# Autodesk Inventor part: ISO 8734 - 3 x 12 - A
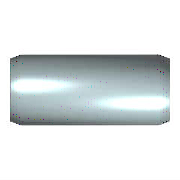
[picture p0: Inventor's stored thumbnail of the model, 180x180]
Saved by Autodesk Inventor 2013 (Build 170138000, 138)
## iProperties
Created: 2012-02
Part Number: ISO 8734 - 3 x 12 - A
Material: Stahl
Description: Zylinderstift
Document SubType Name: Modeling
Standard: ISO 8734
Designer: rYan
Standards Organization: DIN
Language: de-DE
Size Designation: 3 x 12 - A
Categories: <MemberInstance><Categories><Category DisplayName="Verbindungselemente" InternalName="e4da775c-781d-43d5-af7c-5136215cf5a6" Mnemonic="FSTN"><Category DisplayNam
Density: 7.85 g/cm^3
IsCustomPart: 0
Author: rYan
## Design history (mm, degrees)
sketch "Skizze"
  geometry: C1 r 1.5 at (0, 0); 1 further point
  constraints: 1 centre point, 1 coincident
  dimensions: "d1" = 3 diameter of C1 (= NND)
extrude "Körper" new body sketch "Skizze" distance "d2" = 12 (= NLG); taper "d3" = 0 deg
body "Solid1"
chamfer "Fase1" distance "d4" = 0.5 (= PHH); stored, may be unused: angle "d5" = 15 deg (= FAWI), second distance "d11" = 0.5 (= PHH)
chamfer "Fase2" distance "d8" = 0.5 (= PHH); stored, may be unused: angle "d9" = 15 deg (= FAWI), second distance "d12" = 0.5 (= PHH)
other parameters: "NND" = 3 [user parameter; used in 1 equation term], "NLG" = 12 [user parameter; used in 1 equation term], "PHH" = 0.5 [user parameter; used in 5 equation terms], "FAWI" = 15 deg [user parameter; used in 2 equation terms], "d13" = 0, "d15" = 0, "d16" = 0, "PHH2" = 0.5 (= PHH) [user parameter], "FAWI2" = 15 deg [user parameter]
